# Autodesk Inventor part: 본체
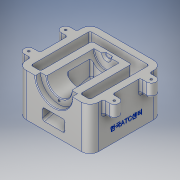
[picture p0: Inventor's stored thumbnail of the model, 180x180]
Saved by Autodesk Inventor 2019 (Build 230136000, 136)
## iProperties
Created: 2022-03
Part Number: 본체
Material: 알루미늄 6061
Document SubType Name: Modeling
Designer: LINE501-2
Density: 2.7 g/cm^3
Appearance: 알루미늄 - 평지
Mass: 1024.1 g
Surface Area: 845.101 cm^2
Volume: 379.298 cm^3
Author: LINE501-2
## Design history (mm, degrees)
sketch "스케치1"
  geometry: L1 (55, -55)-(-55, -55); L2 (-55, -55)-(-55, 55); L3 (-55, 55)-(55, 55); L4 (55, 55)-(55, -55); L5 (-45, 45)-(-45, -45); L6 (-45, -45)-(45, -45); L7 (45, -45)-(45, 45); L8 (45, 45)-(-45, 45); 3 further points
  constraints: 16 end point, 4 parallel, 2 midpoint, 2 perpendicular, 1 horizontal, 1 horizontal alignment, 1 vertical alignment, 3 other
  dimensions: "d0" = 110 distance between parallel lines of L1 L3; "d1" = 110 distance between parallel lines of L4 L2; "d2" = 10 distance between parallel lines of L2 L5
extrude "돌출1" new body sketch "스케치1" distance "d3" = 65; taper "d4" = 0 deg
sketch "스케치2"
  geometry: L1 (-65, 28)-(-55, 28); L2 (-65, 21)-(-55, 21); L3 (-55, 35)-(-65, 35); L4 (-65, -28)-(-55, -28); L5 (-65, -35)-(-55, -35); L6 (-55, -21)-(-65, -21); L7 (55, -28)-(65, -28); L8 (55, -35)-(65, -35); L9 (65, -21)-(55, -21); L10 (55, 28)-(65, 28); L11 (55, 21)-(65, 21); L12 (65, 35)-(55, 35); L13 (55, 55)-(-55, 55) reference; L14 (-55, -55)-(55, -55) reference; L15 (55, 55)-(-55, 55) reference; L16 (-55, 55)-(-55, -55) reference; L17 (-55, -55)-(55, -55) reference; L18 (55, -55)-(55, 55) reference; L19 (-55, 55)-(-55, -55) reference; A1 r 7 centre (-65, 28) between (-65, 35) and (-65, 21); A2 r 7 centre (-55, 28) between (-55, 21) and (-55, 35); A3 r 7 centre (-65, -28) between (-65, -21) and (-65, -35); A4 r 7 centre (-55, -28) between (-55, -35) and (-55, -21); A5 r 7 centre (55, -28) between (55, -21) and (55, -35); A6 r 7 centre (65, -28) between (65, -35) and (65, -21); A7 r 7 centre (55, 28) between (55, 35) and (55, 21); A8 r 7 centre (65, 28) between (65, 21) and (65, 35); 9 further points
  constraints: 32 end point, 16 point on circle, 16 tangent, 8 centre point, 7 midpoint, 7 parallel, 5 vertical alignment, 2 horizontal alignment, 1 horizontal, 2 other
  dimensions: "d5" = 14 diameter of A2; "d6" = 14 diameter of A4; "d7" = 14 diameter of A6; "d8" = 14 diameter of A8; "d9" = 130 distance of L7.end L4.start; "d10" = 130 distance of L10.end L1.start; "d11" = 27 distance between parallel lines of L13 L1; "d13" = 56 distance of L4.start L1.start; "d14" = 10 distance from line of L19 L1.start
extrude "돌출2" join sketch "스케치2" distance "d15" = 20; taper "d16" = 0 deg
sketch "스케치7"
  geometry: L1 (-30, 33)-(30, 33); L2 (30, 33)-(30, -45); L3 (30, -45)-(-30, -45); L4 (-30, -45)-(-30, 33); L5 (-55, -35)-(-55, -55) reference; L6 (-55, -55)-(55, -55) reference; L7 (55, -55)-(55, -35) reference; L8 (55, -35)-(65, -35) reference; L9 (65, -21)-(55, -21) reference; L10 (55, -21)-(55, 21) reference; L11 (55, 21)-(65, 21) reference; L12 (65, 35)-(55, 35) reference; L13 (55, 35)-(55, 55) reference; L14 (55, 55)-(-55, 55) reference; L15 (-55, 55)-(-55, 35) reference; L16 (-55, 35)-(-65, 35) reference; L17 (-65, 21)-(-55, 21) reference; L18 (-55, 21)-(-55, -21) reference; L19 (-55, -21)-(-65, -21) reference; L20 (-65, -35)-(-55, -35) reference; L21 (45, -45)-(-45, -45) reference; L22 (-45, -45)-(-45, 45) reference; L23 (-45, 45)-(45, 45) reference; L24 (45, 45)-(45, -45) reference; L25 (45, -45)-(-45, -45) reference; A1 r 7 centre (65, -28) between (65, -35) and (65, -21) reference; A2 r 7 centre (65, 28) between (65, 21) and (65, 35) reference; A3 r 7 centre (-65, 28) between (-65, 35) and (-65, 21) reference; A4 r 7 centre (-65, -28) between (-65, -21) and (-65, -35) reference; 4 further points
  constraints: 8 end point, 3 midpoint, 2 coincident, 2 parallel, 1 horizontal, 1 perpendicular
  dimensions: "d36" = 60 distance between parallel lines of L2 L4; "d37" = 88 distance between parallel lines of L6 L1
extrude "돌출5" join sketch "스케치7" distance "d38" = 65; taper "d39" = 0 deg
sketch "스케치3"
  geometry: L1 (65, 55)-(65, 35) reference; L2 (0, 55)-(65, 55) reference; L3 (65, 55)-(65, -25); L4 (65, 21)-(65, -21) reference; L5 (65, -25)-(46, -25); L6 (46, -25)-(46, 47); L7 (46, 47)-(37, 47); L8 (37, 47)-(37, 55); 1 further point
  constraints: 10 end point, 3 perpendicular, 2 point on line, 1 horizontal
  dimensions: "d17" = 8 distance between parallel lines of L2 L7; "d18" = 72 distance between parallel lines of L7 L5; "d19" = 19 distance between parallel lines of L1 L6; "d20" = 28 distance between parallel lines of L1 L8
revolve "회전1" sketch "스케치3" stored, may be unused: angle "d21" = 180 deg
sketch "스케치4"
  geometry: L1 (65, -35)-(65, -55) reference; L2 (65, -33)-(30, -33); L3 (30, -33)-(9.1, 45); L4 (9.1, 45)-(0, 45); L5 (0, -55)-(0, 55) reference; L6 (0, 45)-(0, -45); L7 (0, -45)-(65, -45); L8 (65, -45)-(65, -33); L9 (0, -55)-(65, -55) reference; L10 (0, 55)-(65, 55) reference; 1 further point
  constraints: 12 end point, 3 point on line, 2 horizontal, 1 parallel, 1 perpendicular
  dimensions: "d22" = 22 distance between parallel lines of L2 L9; "d23" = 30 distance from line of L5 L2.end; "d24" = 75 deg angle of L3 L2; "d25" = 10 distance between parallel lines of L10 L4; "d26" = 10 distance between parallel lines of L9 L7
extrude "돌출3" cut sketch "스케치4" stored distance "d27" = 90; taper "d28" = 0 deg
sketch "스케치5"
  geometry: L1 (46, 47)-(46, -25) reference; L2 (31.425, -19)-(11.597, 55); L3 (38.843, 19)-(29.197, 55); L4 (38.843, 19)-(65, 19); L5 (31.425, -19)-(65, -19); L6 (37, 55)-(65, 55) reference; L7 (0, 55)-(65, 55) reference; L8 (11.597, 55)-(29.197, 55); L9 (9.1, 45)-(30, -33) reference; L10 (65, -25)-(65, 47) reference; L11 (65, 19)-(65, -19); 1 further point
  constraints: 12 end point, 4 point on line, 3 horizontal, 1 collinear, 1 parallel
  dimensions: "d30" = 17 distance between parallel lines of L2 L3; "d31" = 36 distance between parallel lines of L4 L6; "d32" = 38 distance between parallel lines of L5 L4; "d40" = 5 distance between parallel lines of L2 L9
extrude "돌출4" cut sketch "스케치5" stored distance "d34" = 34; taper "d35" = 0 deg
sketch "스케치9"
  geometry: L1 (-19, 25)-(19, 25) reference; L2 (-30, 33)-(30, 33) reference; L3 (19, 25)-(-19, 25) reference; L4 (0, 25)-(0, 29); L5 (0, 29)-(-5.191, 29); L6 (-5.191, 29)-(-7.5, 25); L7 (-7.5, 25)-(0, 25); 1 further point
  constraints: 8 end point, 1 collinear, 1 midpoint, 1 perpendicular, 1 point on line, 1 vertical
  dimensions: "d44" = 7.5 distance from line of L4 L6.end; "d45" = 30 deg angle of L4 L6; "d46" = 4 distance between parallel lines of L1 L5
revolve "회전2" sketch "스케치9" stored, may be unused: angle "d47" = 180 deg
sketch "스케치10"
  geometry: A1 r 28 centre (0, 0) between (-28, 0) and (28, 0) reference; 2 further points
  constraints: 1 vertical alignment
  dimensions: "d48" = 23 distance of A1.centre point (0, -23)
hole "구멍1" sketch "스케치10" at (0, -23) diameter "d49" = 3.242; stored, may be unused: countersink angle "d53" = 90 deg, drill point angle "d55" = 118 deg; dims "d50" = 9, "d51" = 4, "d52" = 2, "d54" = 11
sketch "스케치11"
  geometry: A1 r 7 centre (65, -28) between (65, -35) and (65, -21) reference; A2 r 7 centre (65, 28) between (65, 21) and (65, 35) reference; A3 r 7 centre (-65, 28) between (-65, 35) and (-65, 21) reference; A4 r 7 centre (-65, -28) between (-65, -21) and (-65, -35) reference; 5 further points
  constraints: 4 coincident
hole "구멍2" sketch "스케치11" at (65, -28), (65, 28), (-65, 28), (-65, -28) diameter "d56" = 3.242; stored, may be unused: countersink angle "d60" = 90 deg, drill point angle "d62" = 118 deg; dims "d57" = 9, "d58" = 4, "d59" = 2, "d61" = 11
chamfer "모따기1" distance "d63" = 1; stored, may be unused: second distance "d64" = 2, angle "d65" = 45 deg
fillet "모깎기1" dims "d66" = 13
fillet "모깎기2" dims "d67" = 1
fillet "모깎기3" dims "d68" = 3
fillet "모깎기4" dims "d69" = 3
fillet "모깎기6" dims "d71" = 3
fillet "모깎기7" dims "d72" = 3
sketch "스케치13"
  geometry: L1 (-13, 65)-(-13, 0) reference; L2 (84, 0)-(0, 0) reference; 2 further points
  constraints: 1 other
  dimensions: "d74" = 55 distance from line of point (42, 20) L1; "d75" = 20 distance from line of L2 point (42, 20)
feature "엠보싱1" sketch "스케치13" dims "d76" = 0.5, "d77" = 0
fillet "모깎기9" dims "d78" = 3
node "솔리드1"
node "투영된 루프1"
node "투영된 루프2"
